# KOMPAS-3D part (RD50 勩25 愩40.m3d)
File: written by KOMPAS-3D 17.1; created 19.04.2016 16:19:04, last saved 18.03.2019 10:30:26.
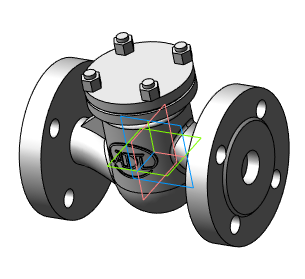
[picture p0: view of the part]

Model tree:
1. Операция без истории:2  (labels: Сталь 20  ГОСТ 1050-88)

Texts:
  RD50 Ду15 Ру40
  RD50 Ду20 Ру40
  RD50 Ду25 Ру40
  RD50 Ду32 Ру40
  RD50 Ду40 Ру40
  RD50 Ду50 Ру40
  RD50 Ду65 Ру40
  RD50 Ду80 Ру40
  RD50 Ду100 Ру40
  RD50 Ду125 Ру40
  RD50 Ду150 Ру40
  RD50 Ду200 Ру40
  RD50 Ду250 Ру40
  RD50 Ду300 Ру40
  RD50 Ду350 Ру40
  RD50 Ду400 Ру40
